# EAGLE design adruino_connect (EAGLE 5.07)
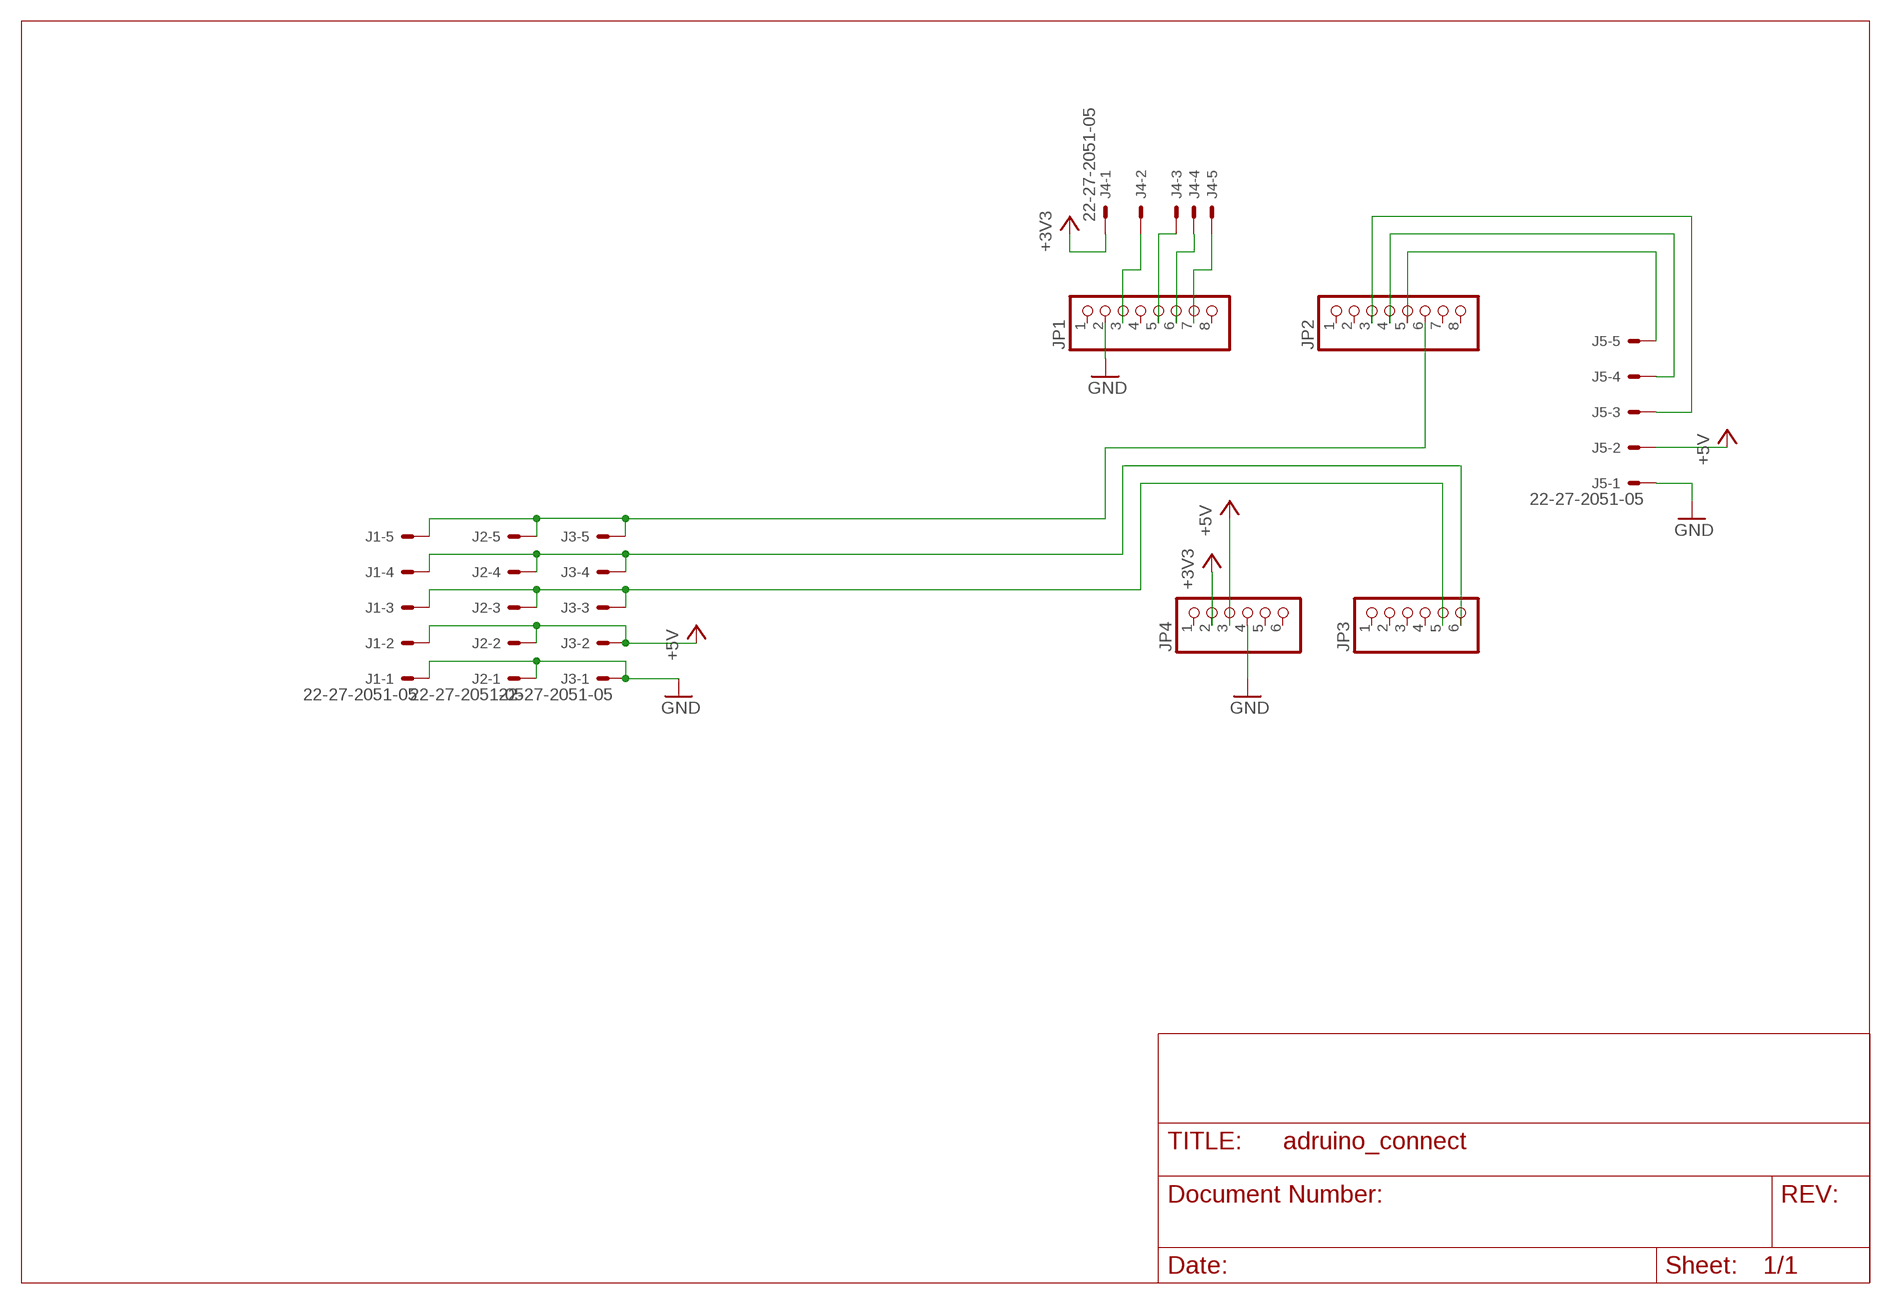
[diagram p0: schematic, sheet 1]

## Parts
J1  22-27-2051-05  [6410-05]
J2  22-27-2051-05  [6410-05]
J3  22-27-2051-05  [6410-05]
J4  22-27-2051-05  [6410-05]
J5  22-27-2051-05  [6410-05]
JP1  PINHD-1X8  [1X08]
JP2  PINHD-1X8  [1X08]
JP3  PINHD-1X6  [1X06]
JP4  PINHD-1X6  [1X06]

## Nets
+3V3: J4.1 JP4.2
+5V: J1.2 J2.2 J3.2 J5.2 JP4.3
GND: J1.1 J2.1 J3.1 J5.1 JP1.2 JP4.4
N$1: J5.5 JP2.5
N$2: J5.4 JP2.4
N$3: J5.3 JP2.3
N$5: J1.3 J2.3 J3.3 JP3.5
N$6: J1.4 J2.4 J3.4 JP3.6
N$7: J1.5 J2.5 J3.5 JP2.6
N$10: J4.5 JP1.7
N$11: J4.4 JP1.6
N$12: J4.2 JP1.3
N$13: J4.3 JP1.5
Unconnected: JP1.1 JP1.4 JP1.8 JP2.1 JP2.2 JP2.7 JP2.8 JP3.1 JP3.2 JP3.3 JP3.4 JP4.1 JP4.5 JP4.6

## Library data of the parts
J1-J5 = con-molex:22-?-05: CONNECTOR wire to board 2.54 mm (.1 inch) pitch header
JP1 JP2 = pinhead:PINHD-1X8: PIN HEADER
JP3 JP4 = pinhead:PINHD-1X6: PIN HEADER

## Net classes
0 default: width 1.27 mm, clearance 0.813 mm

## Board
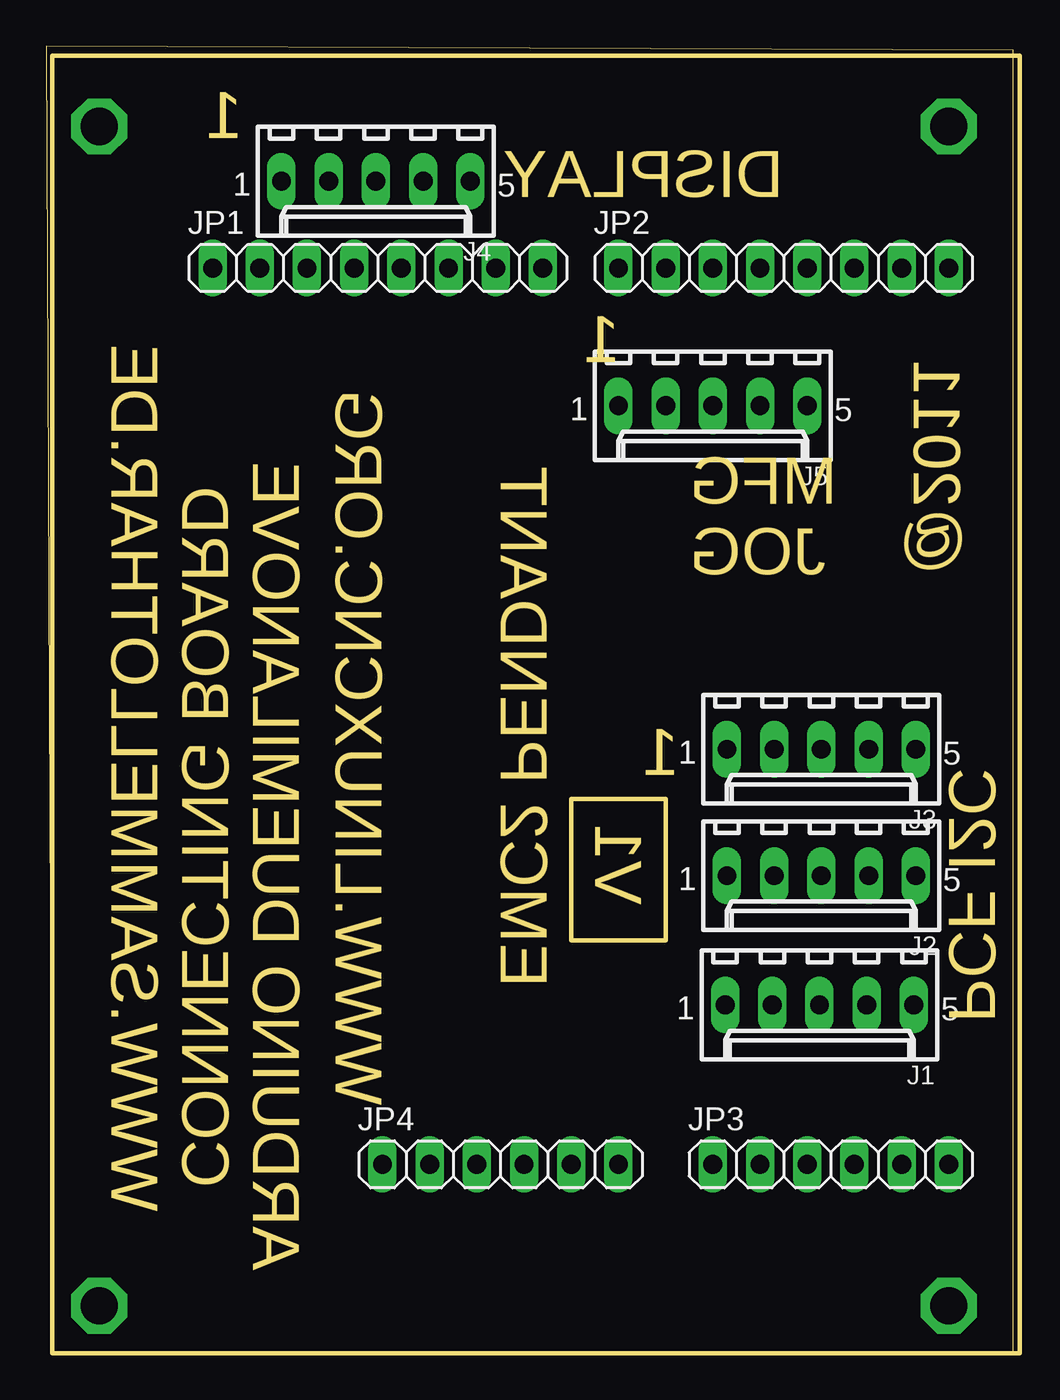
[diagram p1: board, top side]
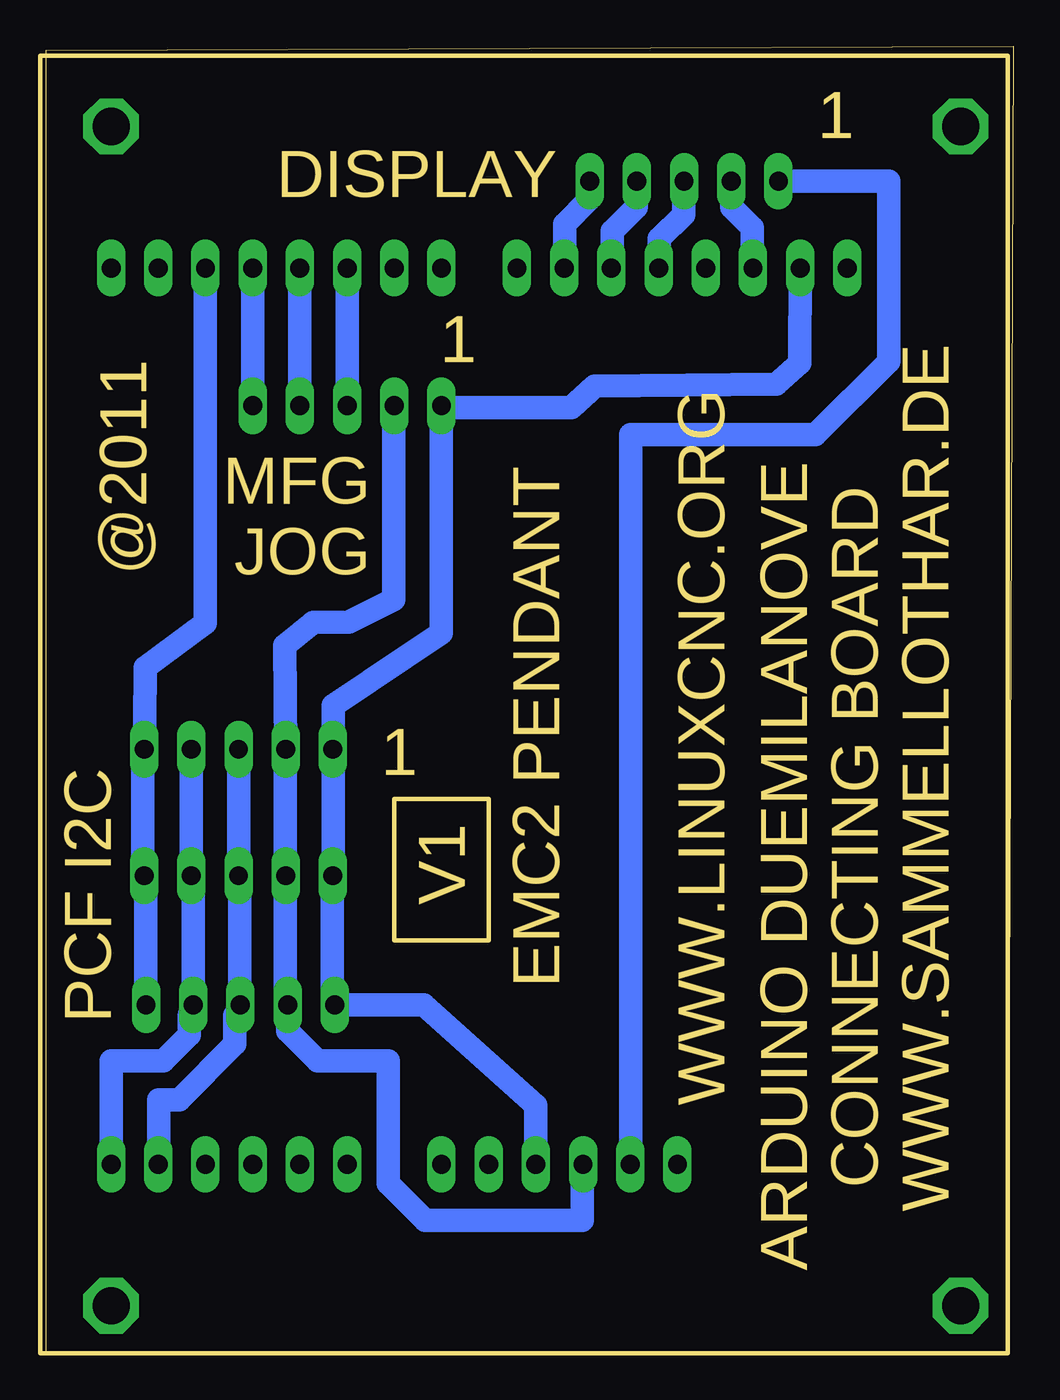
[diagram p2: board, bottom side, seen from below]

Size 52.04 x 70.35 mm. Coordinates in mm from the lower left corner, seen from the top.
Outline: 0.3,0 52.04,0 52.04,70.14 0,70.35 0.3,0
Copper layers (1*16): Top 0.035mm / dielectric 1.5mm / Bottom 0.035mm
Design rules "default": minimum track width 10mil, minimum drill 24mil, track to track 8mil, track to pad 8mil, pad to pad 8mil, via to via 8mil, smd to smd 8mil, copper to edge 40mil, drill to drill 8mil, minimum pad ring 10mil, minimum via ring 8mil, stop-mask expansion 4mil, vias tented up to drill 0mil, thermal gap 10mil
Milling: 8 lines

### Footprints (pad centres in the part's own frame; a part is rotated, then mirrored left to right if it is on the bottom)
6410-05 = drill 1.016 long: 1 5.08,0; 2 2.54,0; 3 0,0; 4 -2.54,0; 5 -5.08,0
1X08 = drill 1.016 long: 1 -8.89,0; 2 -6.35,0; 3 -3.81,0; 4 -1.27,0; 5 1.27,0; 6 3.81,0; 7 6.35,0; 8 8.89,0
1X06 = drill 1.016 long: 1 -6.35,0; 2 -3.81,0; 3 -1.27,0; 4 1.27,0; 5 3.81,0; 6 6.35,0

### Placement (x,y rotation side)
J1  41.61,18.75 180 top
J2  41.71,25.7 180 top
J3  41.71,32.51 180 top
J4  17.73,63.09 180 top
J5  35.86,51 180 top
JP1  17.83,58.42 0 top
JP2  39.67,58.42 0 top
JP3  42.21,10.16 0 top
JP4  24.43,10.16 0 top

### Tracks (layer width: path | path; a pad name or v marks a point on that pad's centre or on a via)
+3V3
  Bottom 1.27: JP4.2 20.6,10.19 20.6,49.44 10.65,49.44 6.7,53.39 6.7,63.09 12.6,63.09 J4.1
+5V
  Bottom 1.27: JP4.3 23.2,10.14 23.2,7.14 31.65,7.14 33.65,9.14 33.65,15.74 37.45,15.74 39.05,17.34 J1.2 39.2,19.34 39.2,25.69 J2.2 39.2,26.34 39.2,32.49 J3.2 39.22,38.1 37.69,39.32 35.78,39.35 33.35,40.57 33.35,50.99 J5.2
GND
  Bottom 1.27: JP4.4 25.7,13.34 31.74,18.74 36.5,18.74 J1.1 36.65,19.34 36.65,25.69 J2.1 36.6,26.34 36.6,32.49 J3.1 36.61,34.87 30.8,38.76 30.8,50.99 J5.1 30.45,50.91 23.8,50.91 22.53,52.07 12.77,52.17 11.5,53.31 JP1.2
N$1
  Bottom 1.27: J5.5 40.95,51.04 40.95,58.39 JP2.5
N$2
  Bottom 1.27: J5.4 JP2.4
N$3
  Bottom 1.27: J5.3 35.85,51.04 35.85,58.39 JP2.3
N$4  (via drill 2)
  other vias: 2.84,66.04
N$5
  Bottom 1.27: JP3.5 46,10.19 46,13.64 44.9,13.64 41.9,16.64 41.9,18.19 J1.3 41.65,18.79 41.65,25.69 J2.3 41.7,26.34 41.7,32.49 J3.3
N$6
  Bottom 1.27: J3.4 44.25,32.49 44.25,26.34 J2.4 44.2,25.69 44.15,25.69 44.15,18.79 J1.4 44.35,18.14 44.35,17.14 45.75,15.74 48.55,15.74 48.55,10.19 JP3.6
N$7
  Bottom 1.27: J1.5 46.7,18.79 46.7,25.69 46.75,25.69 J2.5 46.85,26.34 46.85,31.89 J3.5 46.75,32.54 46.75,33.94 46.73,36.91 43.5,39.3 43.5,58.39 JP2.6
N$8  (via drill 2)
  other vias: 48.56,66.04
N$9  (via drill 2)
  other vias: 48.56,2.54
N$10
  Bottom 1.27: J4.5 22.85,63.09 22.85,62.09 24.15,60.79 24.15,58.44 JP1.7
N$11
  Bottom 1.27: JP1.6 21.6,58.44 21.6,60.39 20.3,61.69 20.3,63.09 J4.4
N$12
  Bottom 1.27: JP1.3 14.05,58.44 14.05,60.59 15.15,61.69 15.15,63.09 J4.2
N$13
  Bottom 1.27: JP1.5 19.05,58.44 19.05,59.99 17.75,61.29 17.75,63.09 J4.3
N$14  (via drill 2)
  other vias: 2.84,2.54

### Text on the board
Milling: 1 | DISPLAY | 1 | MFG | JOG | @2011 | 1 | V1 | EMC2 PENDANT | PCF I2C | WWW.LINUXCNC.ORG | CONNECTING BOARD | WWW.SAMMELLOTHAR.DE | ARDUINO DUEMILANOVE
